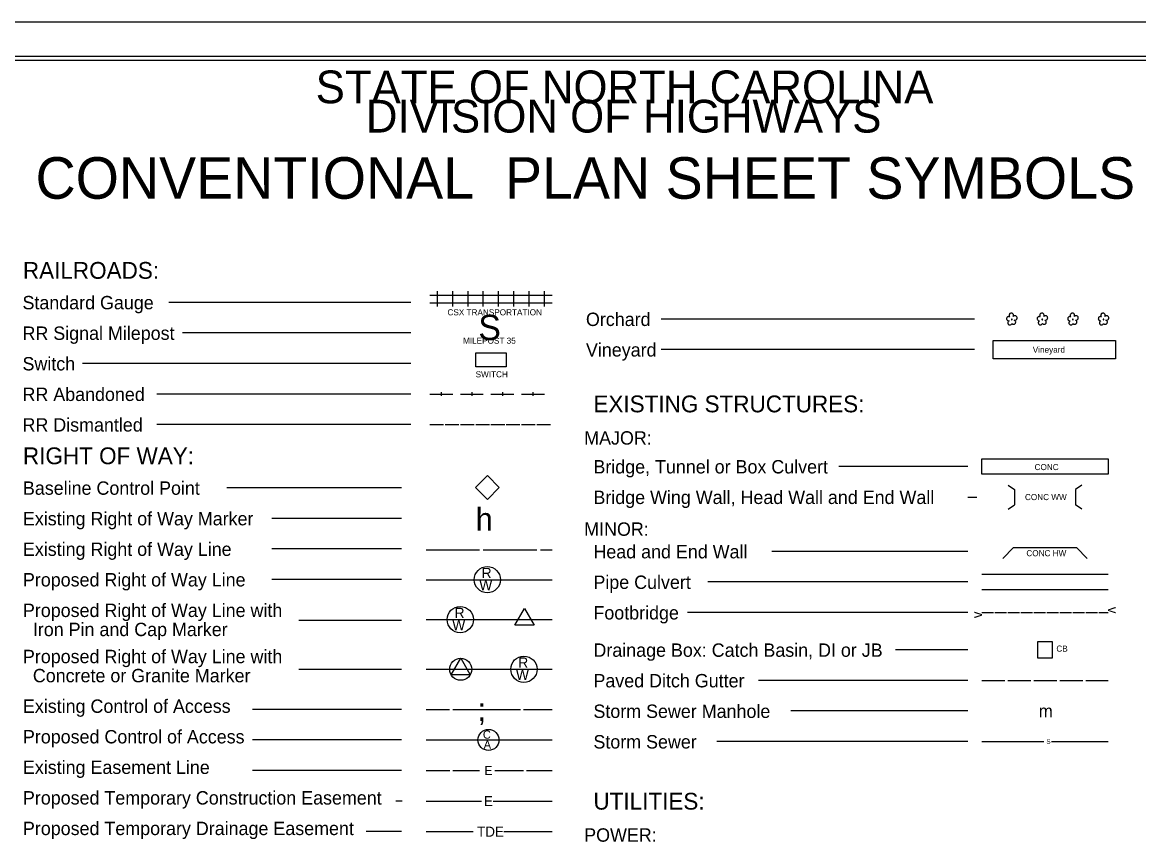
# Model space of a CAD drawing. Extents: x 1513414 to 1532852, y 643392 to 657912.
# Drawn here: x 1528586 to 1529316, y 643953 to 644492 of the extents above; entities that cross this region are included whole.
import ezdxf

# ---------------------------------------------------------------- set-up
doc = ezdxf.new("R2010")
doc.units = 0
for name, color, linetype in [('Prop Shade Light', 7, 'Continuous'), ('Sheet Cutting Line CELL', 7, 'Continuous'), ('Sheet Plot Border Inside CELL', 7, 'Continuous'), ('Sheet Plot Border Outside CELL', 7, 'Continuous'), ('Sheet Symbology CELL', 7, 'Continuous')]:
    doc.layers.add(name, color=color, linetype=linetype)

# ---------------------------------------------------------------- blocks, each defined once
blk = doc.blocks.new('PRRM')
at = {"layer": 'Sheet Symbology CELL'}
blk.add_line((0, 0), (0, 0), dxfattribs=at)
blk.add_lwpolyline([(-0.125, -0.072), (0, 0.144), (0.125, -0.072)], close=True, dxfattribs=at)
blk = doc.blocks.new('RWCON')
at = {"layer": 'Sheet Symbology CELL'}
blk.add_line((0, 0), (0, 0), dxfattribs=at)
blk.add_lwpolyline([(-0.125, -0.072), (0, 0.144), (0.125, -0.072)], close=True, dxfattribs=at)
blk.add_circle((0, 0), 0.144, dxfattribs=at)

msp = doc.modelspace()

# ---------------------------------------------------------------- linework, layer by layer
at = {"layer": 'Prop Shade Light'}
msp.add_lwpolyline([(1528882.43, 644187.15), (1528890.25, 644194.97), (1528898.07, 644187.15), (1528890.25, 644179.32)], close=True, dxfattribs=at)
at = {"layer": 'Sheet Cutting Line CELL'}
msp.add_line((1529708.61, 644491.59), (1528024.61, 644491.59), dxfattribs=at)
at = {"layer": 'Sheet Plot Border Inside CELL'}
msp.add_lwpolyline([(1528037.61, 643414.04), (1529704.11, 643414.04), (1529704.11, 644469.14), (1528037.61, 644469.14)], close=True, dxfattribs=at)
at = {"layer": 'Sheet Plot Border Outside CELL'}
msp.add_lwpolyline([(1528024.61, 643391.59), (1529708.61, 643391.59), (1529708.61, 644491.59), (1528024.61, 644491.59)], close=True, dxfattribs=at)
at = {"layer": 'Sheet Symbology CELL'}
for p, q in [((1528857.61, 644305.57), (1528857.61, 644315.57)), ((1528867.61, 644305.57), (1528867.61, 644315.57)), ((1528877.61, 644305.57), (1528877.61, 644315.57)), ((1528887.61, 644305.57), (1528887.61, 644315.57)), ((1528897.61, 644305.57), (1528897.61, 644315.57)), ((1528907.61, 644305.57), (1528907.61, 644315.57)), ((1528917.61, 644305.57), (1528917.61, 644315.57)), ((1528927.61, 644305.57), (1528927.61, 644315.57)), ((1528840.21, 644308.3), (1528681.8, 644308.3)), ((1528852.61, 644313.07), (1528862.61, 644313.07)), ((1528852.61, 644308.07), (1528862.61, 644308.07)), ((1528862.61, 644313.07), (1528872.61, 644313.07)), ((1528862.61, 644308.07), (1528872.61, 644308.07)), ((1528872.61, 644313.07), (1528882.61, 644313.07)), ((1528872.61, 644308.07), (1528882.61, 644308.07)), ((1528882.61, 644313.07), (1528892.61, 644313.07)), ((1528882.61, 644308.07), (1528892.61, 644308.07)), ((1528892.61, 644313.07), (1528902.61, 644313.07)), ((1528892.61, 644308.07), (1528902.61, 644308.07)), ((1528902.61, 644313.07), (1528912.61, 644313.07)), ((1528902.61, 644308.07), (1528912.61, 644308.07)), ((1528912.61, 644313.07), (1528922.61, 644313.07)), ((1528912.61, 644308.07), (1528922.61, 644308.07)), ((1528922.61, 644313.07), (1528932.61, 644313.07)), ((1528922.61, 644308.07), (1528932.61, 644308.07)), ((1529208.94, 644297.37), (1529004, 644297.37)), ((1528840.21, 644288.3), (1528690.66, 644288.3)), ((1529208.94, 644277.37), (1529004, 644277.37)), ((1528840.21, 644268.3), (1528625.3, 644268.3)), ((1528840.21, 644248.3), (1528674.05, 644248.3)), ((1528852.61, 644248.3), (1528867.61, 644248.3)), ((1528860.11, 644249.55), (1528860.11, 644247.05)), ((1528872.61, 644248.3), (1528887.61, 644248.3)), ((1528880.11, 644249.55), (1528880.11, 644247.05)), ((1528892.61, 644248.3), (1528907.61, 644248.3)), ((1528900.11, 644249.55), (1528900.11, 644247.05)), ((1528912.61, 644248.3), (1528927.61, 644248.3)), ((1528920.11, 644249.55), (1528920.11, 644247.05)), ((1528840.21, 644228.3), (1528674.05, 644228.3)), ((1528840.21, 644228.3), (1528674.05, 644228.3)), ((1528852.61, 644228.3), (1528861.61, 644228.3)), ((1528862.61, 644228.3), (1528871.61, 644228.3)), ((1528872.61, 644228.3), (1528881.61, 644228.3)), ((1528882.61, 644228.3), (1528891.61, 644228.3)), ((1528892.61, 644228.3), (1528901.61, 644228.3)), ((1528902.61, 644228.3), (1528911.61, 644228.3)), ((1528912.61, 644228.3), (1528921.61, 644228.3)), ((1528922.61, 644228.3), (1528931.61, 644228.3)), ((1529204.62, 644200.91), (1529120.2, 644200.91)), ((1528834.08, 644186.95), (1528719.86, 644186.95)), ((1529231.07, 644188.77), (1529235.17, 644185.91)), ((1529235.17, 644185.91), (1529235.17, 644175.91)), ((1529279.27, 644188.77), (1529275.17, 644185.91)), ((1529275.17, 644185.91), (1529275.17, 644175.91)), ((1529204.62, 644180.91), (1529210.61, 644180.91)), ((1529231.07, 644173.05), (1529235.17, 644175.91)), ((1529279.27, 644173.05), (1529275.17, 644175.91)), ((1528834.08, 644166.95), (1528749.14, 644166.95)), ((1528834.08, 644146.95), (1528749.14, 644146.95)), ((1528850.11, 644146.38), (1528885.11, 644146.38)), ((1528887.61, 644146.38), (1528922.61, 644146.38)), ((1528925.11, 644146.38), (1528932.61, 644146.38)), ((1529227.47, 644140.76), (1529234.55, 644147.84)), ((1529234.55, 644147.84), (1529275.8, 644147.84)), ((1529275.8, 644147.84), (1529282.87, 644140.76)), ((1529204.62, 644145.34), (1529076.32, 644145.34)), ((1528834.08, 644126.95), (1528749.14, 644126.95)), ((1528850.11, 644126.83), (1528932.61, 644126.83)), ((1529204.62, 644125.34), (1529034.43, 644125.34)), ((1529213.92, 644130.34), (1529296.42, 644130.34)), ((1529213.92, 644120.34), (1529296.42, 644120.34)), ((1529204.62, 644105.34), (1529021.15, 644105.34)), ((1529213.92, 644105.34), (1529221.42, 644105.34)), ((1529222.42, 644105.34), (1529229.92, 644105.34)), ((1529230.92, 644105.34), (1529238.42, 644105.34)), ((1529239.42, 644105.34), (1529246.92, 644105.34)), ((1529247.92, 644105.34), (1529255.42, 644105.34)), ((1529256.42, 644105.34), (1529263.92, 644105.34)), ((1529264.92, 644105.34), (1529272.42, 644105.34)), ((1529273.42, 644105.34), (1529280.92, 644105.34)), ((1529281.92, 644105.34), (1529289.42, 644105.34)), ((1529290.42, 644105.34), (1529296.42, 644105.34)), ((1528834.08, 644100.1), (1528766.96, 644100.1)), ((1528850.11, 644100.7), (1528932.61, 644100.7)), ((1529204.62, 644080.91), (1529157.42, 644080.91)), ((1528834.08, 644068.07), (1528766.96, 644068.07)), ((1528850.11, 644068.2), (1528932.61, 644068.2)), ((1529204.62, 644060.91), (1529067.67, 644060.91)), ((1529213.92, 644060.91), (1529228.92, 644060.91)), ((1529230.92, 644060.91), (1529245.92, 644060.91)), ((1529247.92, 644060.91), (1529262.92, 644060.91)), ((1529264.92, 644060.91), (1529279.92, 644060.91)), ((1529281.92, 644060.91), (1529296.42, 644060.91)), ((1528834.08, 644041.95), (1528736.53, 644041.95)), ((1528850.11, 644041.95), (1528865.57, 644041.95)), ((1528867.57, 644041.95), (1528911.98, 644041.95)), ((1528913.98, 644041.95), (1528932.61, 644041.95)), ((1529204.62, 644040.91), (1529088.95, 644040.91)), ((1528834.08, 644021.95), (1528736.53, 644021.95)), ((1528850.11, 644021.95), (1528932.61, 644021.95)), ((1529204.62, 644020.91), (1529040.42, 644020.91)), ((1529213.92, 644020.91), (1529254.45, 644020.91)), ((1529259.45, 644020.91), (1529296.42, 644020.91)), ((1528834.08, 644001.95), (1528736.53, 644001.95)), ((1528850.11, 644001.95), (1528865.62, 644001.95)), ((1528867.62, 644001.95), (1528885.12, 644001.95)), ((1528895.12, 644001.95), (1528913.87, 644001.95)), ((1528915.87, 644001.95), (1528932.61, 644001.95)), ((1528834.46, 643981.95), (1528830.29, 643981.95)), ((1528850.11, 643981.95), (1528852.72, 643981.95)), ((1528852.72, 643981.95), (1528886.47, 643981.95)), ((1528893.97, 643981.95), (1528927.72, 643981.95)), ((1528927.72, 643981.95), (1528932.61, 643981.95)), ((1528834.08, 643961.95), (1528810.93, 643961.95)), ((1528850.11, 643961.95), (1528853.46, 643961.95)), ((1528853.46, 643961.95), (1528880.96, 643961.95)), ((1528900.96, 643961.95), (1528928.46, 643961.95)), ((1528928.46, 643961.95), (1528932.61, 643961.95))]:
    msp.add_line(p, q, dxfattribs=at)
for points in [[(1529691.61, 644466.59), (1528191.61, 644466.59), (1528191.61, 643417.61), (1529691.61, 643417.61)], [(1528882.61, 644275.27), (1528902.61, 644275.27), (1528902.61, 644266.17), (1528882.61, 644266.17)], [(1529250.36, 644075.6), (1529259.97, 644075.6), (1529259.97, 644086.23), (1529250.36, 644086.23)]]:
    msp.add_lwpolyline(points, close=True, dxfattribs=at)
for points in [[(1529234.38, 644299.12), (1529234.53, 644299.42), (1529234.58, 644299.72), (1529234.53, 644300.02), (1529234.48, 644300.32), (1529234.33, 644300.57), (1529234.18, 644300.82), (1529233.93, 644301.02), (1529233.68, 644301.17), (1529233.33, 644301.27), (1529233.08, 644301.27), (1529232.78, 644301.22), (1529232.48, 644301.12), (1529232.23, 644300.97), (1529231.98, 644300.77), (1529231.83, 644300.47), (1529231.73, 644300.22), (1529231.68, 644299.92), (1529231.68, 644299.62), (1529231.73, 644299.32), (1529231.88, 644299.07), (1529232.08, 644298.77), (1529231.83, 644298.92), (1529231.53, 644298.97), (1529231.23, 644298.97), (1529230.98, 644298.87), (1529230.73, 644298.77), (1529230.48, 644298.57), (1529230.28, 644298.37), (1529230.13, 644298.12), (1529230.08, 644297.87), (1529230.03, 644297.52), (1529230.08, 644297.27), (1529230.18, 644297.02), (1529230.38, 644296.77), (1529230.53, 644296.57), (1529230.78, 644296.42), (1529231.08, 644296.27), (1529231.33, 644296.22), (1529231.63, 644296.22), (1529231.38, 644296.12), (1529231.13, 644295.92), (1529230.98, 644295.72), (1529230.88, 644295.42), (1529230.78, 644295.12), (1529230.78, 644294.87), (1529230.83, 644294.57), (1529230.98, 644294.32), (1529231.13, 644294.07), (1529231.33, 644293.87), (1529231.58, 644293.72), (1529231.83, 644293.62), (1529232.13, 644293.62), (1529232.43, 644293.62), (1529232.68, 644293.67), (1529232.93, 644293.87), (1529233.18, 644294.02), (1529233.43, 644294.47)], [(1529233.43, 644294.47), (1529234.03, 644294.12), (1529234.33, 644294.02), (1529234.63, 644293.97), (1529234.93, 644294.02), (1529235.18, 644294.12), (1529235.43, 644294.27), (1529235.68, 644294.47), (1529235.83, 644294.72), (1529235.93, 644294.97), (1529236.03, 644295.27), (1529235.98, 644295.57), (1529235.93, 644295.87), (1529235.73, 644296.17), (1529235.58, 644296.37), (1529235.33, 644296.52), (1529235.03, 644296.67), (1529235.33, 644296.62), (1529235.68, 644296.62), (1529235.93, 644296.72), (1529236.23, 644296.87), (1529236.48, 644297.02), (1529236.68, 644297.27), (1529236.83, 644297.57), (1529236.88, 644297.87), (1529236.93, 644298.17), (1529236.88, 644298.47), (1529236.78, 644298.77), (1529236.58, 644299.02), (1529236.33, 644299.27), (1529236.08, 644299.42), (1529235.78, 644299.52), (1529235.48, 644299.57), (1529235.18, 644299.57), (1529234.88, 644299.47), (1529234.63, 644299.32), (1529234.38, 644299.12)], [(1529254.38, 644299.12), (1529254.53, 644299.42), (1529254.58, 644299.72), (1529254.53, 644300.02), (1529254.48, 644300.32), (1529254.33, 644300.57), (1529254.18, 644300.82), (1529253.93, 644301.02), (1529253.68, 644301.17), (1529253.33, 644301.27), (1529253.08, 644301.27), (1529252.78, 644301.22), (1529252.48, 644301.12), (1529252.23, 644300.97), (1529251.98, 644300.77), (1529251.83, 644300.47), (1529251.73, 644300.22), (1529251.68, 644299.92), (1529251.68, 644299.62), (1529251.73, 644299.32), (1529251.88, 644299.07), (1529252.08, 644298.77), (1529251.83, 644298.92), (1529251.53, 644298.97), (1529251.23, 644298.97), (1529250.98, 644298.87), (1529250.73, 644298.77), (1529250.48, 644298.57), (1529250.28, 644298.37), (1529250.13, 644298.12), (1529250.08, 644297.87), (1529250.03, 644297.52), (1529250.08, 644297.27), (1529250.18, 644297.02), (1529250.38, 644296.77), (1529250.53, 644296.57), (1529250.78, 644296.42), (1529251.08, 644296.27), (1529251.33, 644296.22), (1529251.63, 644296.22), (1529251.38, 644296.12), (1529251.13, 644295.92), (1529250.98, 644295.72), (1529250.88, 644295.42), (1529250.78, 644295.12), (1529250.78, 644294.87), (1529250.83, 644294.57), (1529250.98, 644294.32), (1529251.13, 644294.07), (1529251.33, 644293.87), (1529251.58, 644293.72), (1529251.83, 644293.62), (1529252.13, 644293.62), (1529252.43, 644293.62), (1529252.68, 644293.67), (1529252.93, 644293.87), (1529253.18, 644294.02), (1529253.43, 644294.47)], [(1529253.43, 644294.47), (1529254.03, 644294.12), (1529254.33, 644294.02), (1529254.63, 644293.97), (1529254.93, 644294.02), (1529255.18, 644294.12), (1529255.43, 644294.27), (1529255.68, 644294.47), (1529255.83, 644294.72), (1529255.93, 644294.97), (1529256.03, 644295.27), (1529255.98, 644295.57), (1529255.93, 644295.87), (1529255.73, 644296.17), (1529255.58, 644296.37), (1529255.33, 644296.52), (1529255.03, 644296.67), (1529255.33, 644296.62), (1529255.68, 644296.62), (1529255.93, 644296.72), (1529256.23, 644296.87), (1529256.48, 644297.02), (1529256.68, 644297.27), (1529256.83, 644297.57), (1529256.88, 644297.87), (1529256.93, 644298.17), (1529256.88, 644298.47), (1529256.78, 644298.77), (1529256.58, 644299.02), (1529256.33, 644299.27), (1529256.08, 644299.42), (1529255.78, 644299.52), (1529255.48, 644299.57), (1529255.18, 644299.57), (1529254.88, 644299.47), (1529254.63, 644299.32), (1529254.38, 644299.12)], [(1529274.38, 644299.12), (1529274.53, 644299.42), (1529274.58, 644299.72), (1529274.53, 644300.02), (1529274.48, 644300.32), (1529274.33, 644300.57), (1529274.18, 644300.82), (1529273.93, 644301.02), (1529273.68, 644301.17), (1529273.33, 644301.27), (1529273.08, 644301.27), (1529272.78, 644301.22), (1529272.48, 644301.12), (1529272.23, 644300.97), (1529271.98, 644300.77), (1529271.83, 644300.47), (1529271.73, 644300.22), (1529271.68, 644299.92), (1529271.68, 644299.62), (1529271.73, 644299.32), (1529271.88, 644299.07), (1529272.08, 644298.77), (1529271.83, 644298.92), (1529271.53, 644298.97), (1529271.23, 644298.97), (1529270.98, 644298.87), (1529270.73, 644298.77), (1529270.48, 644298.57), (1529270.28, 644298.37), (1529270.13, 644298.12), (1529270.08, 644297.87), (1529270.03, 644297.52), (1529270.08, 644297.27), (1529270.18, 644297.02), (1529270.38, 644296.77), (1529270.53, 644296.57), (1529270.78, 644296.42), (1529271.08, 644296.27), (1529271.33, 644296.22), (1529271.63, 644296.22), (1529271.38, 644296.12), (1529271.13, 644295.92), (1529270.98, 644295.72), (1529270.88, 644295.42), (1529270.78, 644295.12), (1529270.78, 644294.87), (1529270.83, 644294.57), (1529270.98, 644294.32), (1529271.13, 644294.07), (1529271.33, 644293.87), (1529271.58, 644293.72), (1529271.83, 644293.62), (1529272.13, 644293.62), (1529272.43, 644293.62), (1529272.68, 644293.67), (1529272.93, 644293.87), (1529273.18, 644294.02), (1529273.43, 644294.47)], [(1529273.43, 644294.47), (1529274.03, 644294.12), (1529274.33, 644294.02), (1529274.63, 644293.97), (1529274.93, 644294.02), (1529275.18, 644294.12), (1529275.43, 644294.27), (1529275.68, 644294.47), (1529275.83, 644294.72), (1529275.93, 644294.97), (1529276.03, 644295.27), (1529275.98, 644295.57), (1529275.93, 644295.87), (1529275.73, 644296.17), (1529275.58, 644296.37), (1529275.33, 644296.52), (1529275.03, 644296.67), (1529275.33, 644296.62), (1529275.68, 644296.62), (1529275.93, 644296.72), (1529276.23, 644296.87), (1529276.48, 644297.02), (1529276.68, 644297.27), (1529276.83, 644297.57), (1529276.88, 644297.87), (1529276.93, 644298.17), (1529276.88, 644298.47), (1529276.78, 644298.77), (1529276.58, 644299.02), (1529276.33, 644299.27), (1529276.08, 644299.42), (1529275.78, 644299.52), (1529275.48, 644299.57), (1529275.18, 644299.57), (1529274.88, 644299.47), (1529274.63, 644299.32), (1529274.38, 644299.12)], [(1529294.38, 644299.12), (1529294.53, 644299.42), (1529294.58, 644299.72), (1529294.53, 644300.02), (1529294.48, 644300.32), (1529294.33, 644300.57), (1529294.18, 644300.82), (1529293.93, 644301.02), (1529293.68, 644301.17), (1529293.33, 644301.27), (1529293.08, 644301.27), (1529292.78, 644301.22), (1529292.48, 644301.12), (1529292.23, 644300.97), (1529291.98, 644300.77), (1529291.83, 644300.47), (1529291.73, 644300.22), (1529291.68, 644299.92), (1529291.68, 644299.62), (1529291.73, 644299.32), (1529291.88, 644299.07), (1529292.08, 644298.77), (1529291.83, 644298.92), (1529291.53, 644298.97), (1529291.23, 644298.97), (1529290.98, 644298.87), (1529290.73, 644298.77), (1529290.48, 644298.57), (1529290.28, 644298.37), (1529290.13, 644298.12), (1529290.08, 644297.87), (1529290.03, 644297.52), (1529290.08, 644297.27), (1529290.18, 644297.02), (1529290.38, 644296.77), (1529290.53, 644296.57), (1529290.78, 644296.42), (1529291.08, 644296.27), (1529291.33, 644296.22), (1529291.63, 644296.22), (1529291.38, 644296.12), (1529291.13, 644295.92), (1529290.98, 644295.72), (1529290.88, 644295.42), (1529290.78, 644295.12), (1529290.78, 644294.87), (1529290.83, 644294.57), (1529290.98, 644294.32), (1529291.13, 644294.07), (1529291.33, 644293.87), (1529291.58, 644293.72), (1529291.83, 644293.62), (1529292.13, 644293.62), (1529292.43, 644293.62), (1529292.68, 644293.67), (1529292.93, 644293.87), (1529293.18, 644294.02), (1529293.43, 644294.47)], [(1529293.43, 644294.47), (1529294.03, 644294.12), (1529294.33, 644294.02), (1529294.63, 644293.97), (1529294.93, 644294.02), (1529295.18, 644294.12), (1529295.43, 644294.27), (1529295.68, 644294.47), (1529295.83, 644294.72), (1529295.93, 644294.97), (1529296.03, 644295.27), (1529295.98, 644295.57), (1529295.93, 644295.87), (1529295.73, 644296.17), (1529295.58, 644296.37), (1529295.33, 644296.52), (1529295.03, 644296.67), (1529295.33, 644296.62), (1529295.68, 644296.62), (1529295.93, 644296.72), (1529296.23, 644296.87), (1529296.48, 644297.02), (1529296.68, 644297.27), (1529296.83, 644297.57), (1529296.88, 644297.87), (1529296.93, 644298.17), (1529296.88, 644298.47), (1529296.78, 644298.77), (1529296.58, 644299.02), (1529296.33, 644299.27), (1529296.08, 644299.42), (1529295.78, 644299.52), (1529295.48, 644299.57), (1529295.18, 644299.57), (1529294.88, 644299.47), (1529294.63, 644299.32), (1529294.38, 644299.12)], [(1529233.53, 644297.37), (1529233.38, 644297.37), (1529233.28, 644297.32), (1529233.18, 644297.27), (1529233.18, 644297.12), (1529233.18, 644297.02), (1529233.28, 644296.92), (1529233.43, 644296.92), (1529233.53, 644296.92), (1529233.63, 644297.02), (1529233.68, 644297.17), (1529233.63, 644297.27), (1529233.53, 644297.37)], [(1529253.53, 644297.37), (1529253.38, 644297.37), (1529253.28, 644297.32), (1529253.18, 644297.27), (1529253.18, 644297.12), (1529253.18, 644297.02), (1529253.28, 644296.92), (1529253.43, 644296.92), (1529253.53, 644296.92), (1529253.63, 644297.02), (1529253.68, 644297.17), (1529253.63, 644297.27), (1529253.53, 644297.37)], [(1529273.53, 644297.37), (1529273.38, 644297.37), (1529273.28, 644297.32), (1529273.18, 644297.27), (1529273.18, 644297.12), (1529273.18, 644297.02), (1529273.28, 644296.92), (1529273.43, 644296.92), (1529273.53, 644296.92), (1529273.63, 644297.02), (1529273.68, 644297.17), (1529273.63, 644297.27), (1529273.53, 644297.37)], [(1529293.53, 644297.37), (1529293.38, 644297.37), (1529293.28, 644297.32), (1529293.18, 644297.27), (1529293.18, 644297.12), (1529293.18, 644297.02), (1529293.28, 644296.92), (1529293.43, 644296.92), (1529293.53, 644296.92), (1529293.63, 644297.02), (1529293.68, 644297.17), (1529293.63, 644297.27), (1529293.53, 644297.37)], [(1529221.33, 644283.37), (1529301.33, 644283.37), (1529301.33, 644271.37), (1529221.33, 644271.37), (1529221.33, 644283.37)], [(1529213.92, 644205.91), (1529296.42, 644205.91), (1529296.42, 644195.91), (1529213.92, 644195.91), (1529213.92, 644205.91)]]:
    msp.add_lwpolyline(points, dxfattribs=at)
for centre, radius in [((1528890.23, 644126.83), 8.61), ((1528872.53, 644100.7), 8.61), ((1528914.2, 644068.2), 8.61), ((1528890.98, 644021.95), 6.89)]:
    msp.add_circle(centre, radius, dxfattribs=at)

# ---------------------------------------------------------------- block references
at = {"layer": 'Prop Shade Light', "xscale": 50, "yscale": 50}
for name, p in [('PRRM', (1528914.56, 644100.7)), ('RWCON', (1528872.81, 644068.2))]:
    msp.add_blockref(name, p, dxfattribs=at)

# ---------------------------------------------------------------- texts
at = {"layer": 'Sheet Symbology CELL'}
for s, height, p in [('STATE OF NORTH CAROLINA', 21.419, (1528777.91, 644438.63)), ('DIVISION OF HIGHWAYS', 21.419, (1528810.76, 644419.46)), ('CONVENTIONAL  PLAN SHEET SYMBOLS', 27.2003, (1528594.6, 644376.14)), ('RAILROADS:', 11, (1528586.33, 644323.75)), ('Standard Gauge', 8.75, (1528586.05, 644303.78)), ('S', 16.5, (1528884.37, 644283.68)), ('Orchard', 8.75, (1528954.77, 644292.85)), ('RR Signal Milepost', 8.75, (1528586.05, 644283.78)), ('Vineyard', 8.75, (1528954.77, 644272.85)), ('Switch', 8.75, (1528586.05, 644263.78)), ('RR Abandoned', 8.75, (1528586.05, 644243.78)), ('EXISTING STRUCTURES:', 11, (1528959.66, 644236.36)), ('RR Dismantled', 8.75, (1528586.05, 644223.78)), ('MAJOR:', 8.75, (1528953.63, 644215.24)), ('RIGHT OF WAY:', 11, (1528586.33, 644202.4)), ('Bridge, Tunnel or Box Culvert', 8.75, (1528959.66, 644196.36)), ('CONC', 4, (1529248.36, 644198.55)), ('Baseline Control Point', 8.75, (1528586.33, 644182.4)), ('Bridge Wing Wall, Head Wall and End Wall', 8.75, (1528959.66, 644176.36)), ('h', 15, (1528882.62, 644158.88)), ('Existing Right of Way Marker', 8.75, (1528586.33, 644162.4)), ('MINOR:', 8.75, (1528953.63, 644155.55)), ('Existing Right of Way Line', 8.75, (1528586.33, 644142.4)), ('Head and End Wall', 8.75, (1528959.66, 644140.79)), ('Proposed Right of Way Line', 8.75, (1528586.33, 644122.4)), ('R', 6.75, (1528886.52, 644127.84)), ('W', 6.75, (1528884.98, 644119.89)), ('Pipe Culvert', 8.75, (1528959.66, 644120.8)), ('Proposed Right of Way Line with', 8.75, (1528586.33, 644102.4)), ('Footbridge', 8.75, (1528959.67, 644100.8)), ('R', 6.75, (1528868.82, 644101.72)), ('  Iron Pin and Cap Marker', 8.75, (1528586.33, 644089.9)), ('W', 6.75, (1528867.28, 644093.77)), ('Proposed Right of Way Line with', 8.75, (1528586.33, 644072.19)), ('Drainage Box: Catch Basin, DI or JB', 8.75, (1528959.67, 644076.37)), ('R', 6.75, (1528910.49, 644069.22)), ('  Concrete or Granite Marker', 8.75, (1528586.33, 644059.69)), ('W', 6.75, (1528908.96, 644061.27)), ('Paved Ditch Gutter', 8.75, (1528959.67, 644056.36)), ('Existing Control of Access', 8.75, (1528586.33, 644039.69)), (';', 15, (1528883.86, 644034.45)), ('Storm Sewer Manhole', 8.75, (1528959.67, 644036.36)), ('m', 8.25, (1529251.05, 644036.78)), ('Proposed Control of Access', 8.75, (1528586.33, 644019.69)), ('C', 5.4, (1528887.32, 644022.77)), ('A', 5.4, (1528887.86, 644016.28)), ('Storm Sewer', 8.75, (1528959.67, 644016.36)), ('S', 3, (1529256.05, 644019.41)), ('Existing Easement Line', 8.75, (1528586.33, 643999.69)), ('E', 6, (1528888.32, 643998.95)), ('Proposed Temporary Construction Easement', 8.75, (1528586.33, 643979.69)), ('E', 6.55, (1528888.07, 643978.65)), ('UTILITIES:', 11, (1528959.66, 643976.36)), ('Proposed Temporary Drainage Easement', 8.75, (1528586.33, 643959.69)), ('TDE', 6.55, (1528883.56, 643958.65)), ('POWER:', 8.75, (1528953.63, 643955.37))]:
    msp.add_text(s, height=height, dxfattribs=at).set_placement(p)
for s, height, rotation, p in [('CSX TRANSPORTATION', 4, 360, (1528864.17, 644299.83)), ('MILEPOST 35', 4, 360, (1528874.36, 644281.25)), ('Vineyard', 4, 0.00002, (1529247.15, 644275.37)), ('SWITCH', 4, 360, (1528882.56, 644259.25)), ('CONC WW', 4, 0.00002, (1529242.05, 644178.91)), ('CONC HW', 4, 360, (1529242.97, 644142.18)), ('v', 6.6, 270.24085, (1529296.41, 644109.08)), ('v', 6.6, 89.75915, (1529213.91, 644101.6)), ('CB', 4, 360, (1529262.61, 644079.73))]:
    msp.add_text(s, height=height, rotation=rotation, dxfattribs=at).set_placement(p)

doc.saveas('drawing.dxf')
